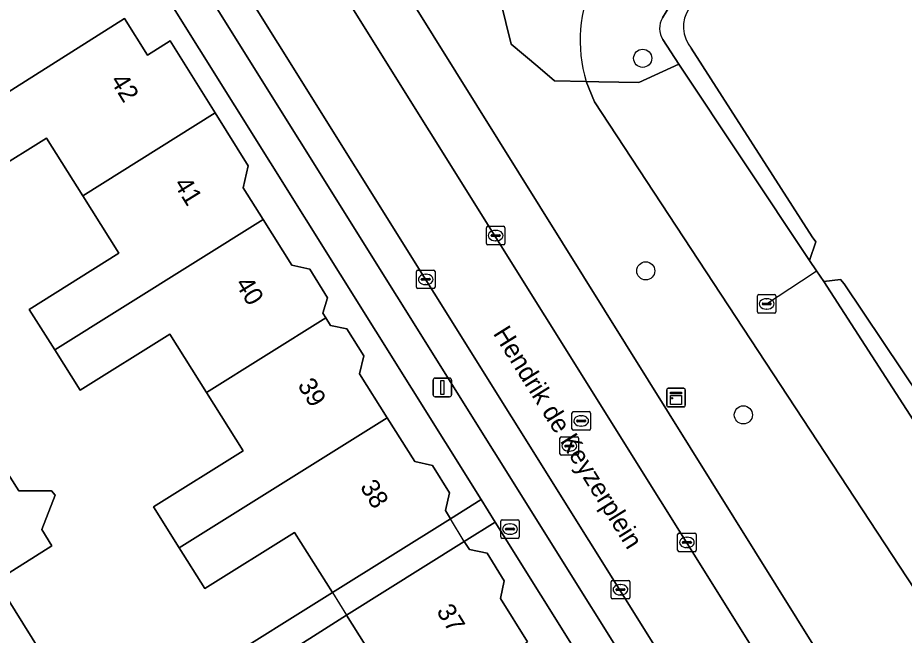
# Model space of a CAD drawing. Extents: x 159664 to 160323, y 385312 to 386115.
# Drawn here: x 159789.65 to 159837.52, y 385916.71 to 385950.06 of the extents above; entities that cross this region are included whole.
import ezdxf

# ---------------------------------------------------------------- set-up
doc = ezdxf.new("R2010")
doc.units = 0
for name, color, linetype in [('IMGEO_Boom', 7, 'Continuous'), ('IMGEO_Brandkraan', 7, 'Continuous'), ('IMGEO_Duiker', 7, 'Continuous'), ('IMGEO_Erf', 7, 'Continuous'), ('IMGEO_Groenvoorziening', 7, 'Continuous'), ('IMGEO_Kast', 7, 'Continuous'), ('IMGEO_Kolk', 7, 'Continuous'), ('IMGEO_Lichtmast', 7, 'Continuous'), ('IMGEO_Meer_plas_ven_vijver', 7, 'Continuous'), ('IMGEO_Oever', 7, 'Continuous'), ('IMGEO_Openbare_ruimte_label', 7, 'Continuous'), ('IMGEO_Pand', 7, 'Continuous'), ('IMGEO_Pand_nummerreeks', 7, 'Continuous'), ('IMGEO_Pand_overbouw', 7, 'Continuous'), ('IMGEO_Parkeervlak_open', 7, 'Continuous'), ('IMGEO_Rijbaan_lokaal_open', 7, 'Continuous'), ('IMGEO_Rioolput', 7, 'Continuous'), ('IMGEO_Voetpad_open', 7, 'Continuous')]:
    doc.layers.add(name, color=color, linetype=linetype)

msp = doc.modelspace()

# ---------------------------------------------------------------- linework, layer by layer
at = {"layer": 'IMGEO_Boom'}
for centre in [(159823.397, 385947.867), (159823.564, 385936.39), (159828.834, 385928.614)]:
    msp.add_circle(centre, 0.489, dxfattribs=at)
at = {"layer": 'IMGEO_Brandkraan'}
for p, q in [((159815.728, 385922.02), (159815.728, 385922.872)), ((159815.803, 385922.946), (159816.655, 385922.946)), ((159816.729, 385922.872), (159816.729, 385922.02)), ((159815.987, 385922.44), (159815.987, 385922.452)), ((159816.425, 385922.403), (159816.027, 385922.403)), ((159816.03, 385922.489), (159816.428, 385922.489)), ((159816.216, 385922.726), (159816.241, 385922.726)), ((159816.471, 385922.452), (159816.471, 385922.44)), ((159816.655, 385921.946), (159815.803, 385921.946)), ((159816.239, 385922.166), (159816.214, 385922.166))]:
    msp.add_line(p, q, dxfattribs=at)
for points in [[(159815.728, 385922.02), (159815.728, 385922.872)], [(159815.803, 385922.946), (159816.655, 385922.946)], [(159816.729, 385922.872), (159816.729, 385922.02)], [(159816.655, 385921.946), (159815.803, 385921.946)]]:
    msp.add_lwpolyline(points, dxfattribs=at)
for centre, radius, start, end in [((159815.805, 385922.87), 0.0765, 91.552, 178.448), ((159815.805, 385922.87), 0.0765, 91.552, 178.448), ((159816.653, 385922.87), 0.0765, 1.552, 88.448), ((159816.653, 385922.87), 0.0765, 1.552, 88.448), ((159816.027, 385922.449), 0.0403, 85.8775, 175.7526), ((159816.024, 385922.439), 0.0366, 178.938, 274.7102), ((159816.428, 385922.446), 0.043, 264.8664, 352.4533), ((159816.432, 385922.451), 0.0386, 1.7309, 96.639), ((159815.805, 385922.022), 0.0765, 181.552, 268.448), ((159815.805, 385922.022), 0.0765, 181.552, 268.448), ((159816.653, 385922.022), 0.0765, 271.552, 358.448), ((159816.653, 385922.022), 0.0765, 271.552, 358.448)]:
    msp.add_arc(centre, radius, start, end, dxfattribs=at)
for centre, major_axis, ratio, start_param, end_param in [((159816.215, 385922.446), (-0.387, 0.002), 0.722429, 4.712389, 7.853982), ((159816.24, 385922.446), (-0.39, 0.002), 0.717154, 1.570796, 4.712389)]:
    msp.add_ellipse(centre, major_axis=major_axis, ratio=ratio, start_param=start_param, end_param=end_param, dxfattribs=at)
at = {"layer": 'IMGEO_Duiker'}
msp.add_lwpolyline([(159830.09, 385934.606), (159832.603, 385936.27), (159832.783, 385936.389)], dxfattribs=at)
at = {"layer": 'IMGEO_Erf'}
for points in [[(159786.659, 385944.493), (159795.419, 385950.015), (159796.66, 385948.031), (159797.888, 385948.804), (159800.312, 385944.919), (159802.091, 385942.069), (159801.831, 385940.872), (159802.903, 385939.167), (159804.456, 385936.699), (159805.426, 385936.473), (159806.378, 385934.929), (159806.13, 385934.103), (159806.288, 385933.852), (159806.542, 385933.446), (159807.423, 385933.265), (159808.337, 385931.801), (159808.106, 385930.83), (159809.598, 385928.459), (159811.09, 385926.088), (159812.048, 385925.874), (159812.959, 385924.403), (159812.75, 385923.441), (159813.015, 385923.006), (159814.677, 385924.046), (159795.686, 385954.403)], [(159781.447, 385937.53), (159789.716, 385924.506), (159791.471, 385924.506), (159791.672, 385924.284), (159790.943, 385922.426), (159791.494, 385921.542), (159788.476, 385919.657), (159793.859, 385911.039), (159806.639, 385919.023), (159804.599, 385922.264), (159799.757, 385919.236), (159798.371, 385921.438), (159796.985, 385923.641), (159801.827, 385926.669), (159799.844, 385929.822), (159797.86, 385932.974), (159793.018, 385929.945), (159791.645, 385932.126), (159790.273, 385934.308), (159795.115, 385937.336), (159793.159, 385940.445), (159791.202, 385943.555), (159788.367, 385941.782)], [(159840.099, 385883.409), (159815.439, 385922.828), (159813.76, 385921.778), (159814.046, 385921.34), (159814.998, 385921.143), (159815.925, 385919.652), (159815.719, 385918.693), (159817.168, 385916.35)], [(159809.423, 385914.598), (159807.404, 385917.807), (159794.696, 385909.716)]]:
    msp.add_lwpolyline(points, dxfattribs=at)
at = {"layer": 'IMGEO_Groenvoorziening'}
for points in [[(159826.198, 385960.753), (159827.558, 385962.925), (159826.053, 385963.543), (159824.666, 385963.973), (159824.14, 385965.264), (159822.897, 385966.316), (159819.555, 385969.187), (159812.339, 385964.66), (159812.663, 385963.686), (159812.807, 385961.678), (159812.472, 385960.291), (159811.468, 385959.287), (159811.037, 385957.804), (159811.994, 385956.513), (159814.146, 385955.461), (159815.58, 385954.17), (159815.963, 385953.118), (159815.724, 385950.966), (159816.297, 385948.623), (159817.732, 385947.428), (159818.628, 385946.65), (159820.348, 385946.616)], [(159816.297, 385948.623), (159815.724, 385950.966), (159815.963, 385953.118), (159815.58, 385954.17), (159814.146, 385955.461), (159811.994, 385956.513), (159811.037, 385957.804), (159811.468, 385959.287), (159812.472, 385960.291), (159812.807, 385961.678), (159812.663, 385963.686), (159812.339, 385964.66), (159805.18, 385960.168), (159840.98, 385902.792), (159844.627, 385901.937), (159897.826, 385935.149), (159897.089, 385936.287), (159896.974, 385936.212), (159896.463, 385937.027)], [(159824.47, 385950.057), (159825.856, 385952.338), (159828.271, 385956.314)], [(159820.348, 385946.616), (159821.022, 385946.602), (159823.184, 385946.559), (159825.341, 385947.546), (159824.488, 385948.875)], [(159838.479, 385918.611), (159820.789, 385945.508), (159820.348, 385946.616), (159818.628, 385946.65), (159817.732, 385947.428), (159816.297, 385948.623)], [(159825.341, 385947.546), (159823.184, 385946.559), (159821.022, 385946.602), (159820.348, 385946.616), (159820.789, 385945.508), (159838.479, 385918.611), (159839.072, 385919.548), (159844.581, 385919.713), (159855.219, 385918.667), (159855.427, 385918.399), (159863.832, 385920.689), (159866.297, 385921.953), (159870.044, 385923.874), (159871.106, 385924.495), (159870.716, 385924.674), (159869.124, 385925.404), (159865.913, 385927.638), (159862.758, 385925.65), (159861.486, 385925.086), (159860.136, 385924.752), (159854.341, 385923.788), (159843.899, 385922.051)], [(159841.353, 385923.154), (159833.178, 385935.808), (159832.783, 385936.389), (159832.404, 385936.945), (159825.341, 385947.546)]]:
    msp.add_lwpolyline(points, dxfattribs=at)
for centre, radius, start, end in [((159827.47, 385948.807), 7.452, 153.2515, 197.0998), ((159827.47, 385948.807), 7.452, 153.2515, 197.0998), ((159825.421, 385949.48), 1.112, 148.7758, 212.9691)]:
    msp.add_arc(centre, radius, start, end, dxfattribs=at)
at = {"layer": 'IMGEO_Kast'}
for p, q in [((159824.695, 385929.123), (159824.695, 385929.964)), ((159824.695, 385929.964), (159824.695, 385929.123)), ((159824.77, 385930.048), (159825.611, 385930.048)), ((159825.611, 385930.048), (159824.77, 385930.048)), ((159825.695, 385929.973), (159825.695, 385929.132)), ((159825.695, 385929.132), (159825.695, 385929.973)), ((159825.62, 385929.048), (159824.779, 385929.048)), ((159824.779, 385929.048), (159825.62, 385929.048))]:
    msp.add_line(p, q, dxfattribs=at)
for points in [[(159824.89, 385929.838), (159825.49, 385929.838), (159825.49, 385929.753), (159824.89, 385929.753), (159824.89, 385929.838)], [(159824.89, 385929.663), (159825.49, 385929.663), (159825.49, 385929.174), (159824.89, 385929.174), (159824.89, 385929.663)]]:
    msp.add_lwpolyline(points, dxfattribs=at)
msp.add_circle((159824.974, 385929.512), 0.0377, dxfattribs=at)
for centre, start, end in [((159824.773, 385929.97), 92.4484, 184.2845), ((159824.773, 385929.97), 92.4484, 184.2845), ((159825.617, 385929.97), 2.4484, 94.2845), ((159825.617, 385929.97), 2.4484, 94.2845), ((159824.773, 385929.126), 182.4484, 274.2845), ((159824.773, 385929.126), 182.4484, 274.2845), ((159825.617, 385929.126), 272.4484, 4.2845), ((159825.617, 385929.126), 272.4484, 4.2845)]:
    msp.add_arc(centre, 0.0779, start, end, dxfattribs=at)
at = {"layer": 'IMGEO_Kolk'}
for p, q in [((159814.959, 385937.868), (159814.959, 385938.72)), ((159815.034, 385938.794), (159815.886, 385938.794)), ((159815.447, 385938.574), (159815.472, 385938.574)), ((159815.96, 385938.72), (159815.96, 385937.868)), ((159815.218, 385938.288), (159815.218, 385938.3)), ((159815.656, 385938.251), (159815.258, 385938.251)), ((159815.261, 385938.337), (159815.659, 385938.337)), ((159815.702, 385938.3), (159815.702, 385938.288)), ((159815.886, 385937.794), (159815.034, 385937.794)), ((159815.47, 385938.014), (159815.445, 385938.014)), ((159811.184, 385935.504), (159811.184, 385936.356)), ((159811.259, 385936.43), (159812.111, 385936.43)), ((159811.672, 385936.21), (159811.697, 385936.21)), ((159812.185, 385936.356), (159812.185, 385935.504)), ((159811.443, 385935.924), (159811.443, 385935.936)), ((159811.881, 385935.887), (159811.483, 385935.887)), ((159811.486, 385935.973), (159811.884, 385935.973)), ((159811.927, 385935.936), (159811.927, 385935.924)), ((159812.111, 385935.43), (159811.259, 385935.43)), ((159811.695, 385935.65), (159811.67, 385935.65)), ((159825.282, 385921.301), (159825.282, 385922.153)), ((159825.357, 385922.227), (159826.209, 385922.227)), ((159825.77, 385922.007), (159825.795, 385922.007)), ((159826.283, 385922.153), (159826.283, 385921.301)), ((159825.541, 385921.721), (159825.541, 385921.733)), ((159825.979, 385921.684), (159825.581, 385921.684)), ((159825.584, 385921.77), (159825.982, 385921.77)), ((159825.793, 385921.447), (159825.768, 385921.447)), ((159826.025, 385921.733), (159826.025, 385921.721)), ((159826.209, 385921.227), (159825.357, 385921.227)), ((159821.697, 385918.748), (159821.697, 385919.6)), ((159821.772, 385919.674), (159822.624, 385919.674)), ((159822.185, 385919.454), (159822.21, 385919.454)), ((159822.698, 385919.6), (159822.698, 385918.748)), ((159821.956, 385919.168), (159821.956, 385919.18)), ((159822.394, 385919.131), (159821.996, 385919.131)), ((159821.999, 385919.217), (159822.397, 385919.217)), ((159822.44, 385919.18), (159822.44, 385919.168)), ((159822.624, 385918.674), (159821.772, 385918.674)), ((159822.208, 385918.894), (159822.183, 385918.894))]:
    msp.add_line(p, q, dxfattribs=at)
for points in [[(159814.959, 385937.868), (159814.959, 385938.72)], [(159815.034, 385938.794), (159815.886, 385938.794)], [(159815.96, 385938.72), (159815.96, 385937.868)], [(159815.886, 385937.794), (159815.034, 385937.794)], [(159811.184, 385935.504), (159811.184, 385936.356)], [(159811.259, 385936.43), (159812.111, 385936.43)], [(159812.185, 385936.356), (159812.185, 385935.504)], [(159812.111, 385935.43), (159811.259, 385935.43)], [(159825.282, 385921.301), (159825.282, 385922.153)], [(159825.357, 385922.227), (159826.209, 385922.227)], [(159826.283, 385922.153), (159826.283, 385921.301)], [(159826.209, 385921.227), (159825.357, 385921.227)], [(159821.697, 385918.748), (159821.697, 385919.6)], [(159821.772, 385919.674), (159822.624, 385919.674)], [(159822.698, 385919.6), (159822.698, 385918.748)], [(159822.624, 385918.674), (159821.772, 385918.674)]]:
    msp.add_lwpolyline(points, dxfattribs=at)
for centre, radius, start, end in [((159815.036, 385938.718), 0.0765, 91.552, 178.448), ((159815.036, 385938.718), 0.0765, 91.552, 178.448), ((159815.884, 385938.718), 0.0765, 1.552, 88.448), ((159815.884, 385938.718), 0.0765, 1.552, 88.448), ((159815.258, 385938.297), 0.0403, 85.8775, 175.7526), ((159815.255, 385938.287), 0.0366, 178.938, 274.7102), ((159815.659, 385938.294), 0.043, 264.8664, 352.4533), ((159815.663, 385938.299), 0.0386, 1.7309, 96.639), ((159815.036, 385937.87), 0.0765, 181.552, 268.448), ((159815.036, 385937.87), 0.0765, 181.552, 268.448), ((159815.884, 385937.87), 0.0765, 271.552, 358.448), ((159815.884, 385937.87), 0.0765, 271.552, 358.448), ((159811.261, 385936.354), 0.0765, 91.552, 178.448), ((159811.261, 385936.354), 0.0765, 91.552, 178.448), ((159812.109, 385936.354), 0.0765, 1.552, 88.448), ((159812.109, 385936.354), 0.0765, 1.552, 88.448), ((159811.483, 385935.933), 0.0403, 85.8775, 175.7526), ((159811.48, 385935.923), 0.0366, 178.938, 274.7102), ((159811.884, 385935.93), 0.043, 264.8664, 352.4533), ((159811.888, 385935.935), 0.0386, 1.7309, 96.639), ((159811.261, 385935.506), 0.0765, 181.552, 268.448), ((159811.261, 385935.506), 0.0765, 181.552, 268.448), ((159812.109, 385935.506), 0.0765, 271.552, 358.448), ((159812.109, 385935.506), 0.0765, 271.552, 358.448), ((159825.359, 385922.151), 0.0765, 91.552, 178.448), ((159825.359, 385922.151), 0.0765, 91.552, 178.448), ((159826.207, 385922.151), 0.0765, 1.552, 88.448), ((159826.207, 385922.151), 0.0765, 1.552, 88.448), ((159825.581, 385921.73), 0.0403, 85.8775, 175.7526), ((159825.578, 385921.72), 0.0366, 178.938, 274.7102), ((159825.982, 385921.727), 0.043, 264.8664, 352.4533), ((159825.986, 385921.732), 0.0386, 1.7309, 96.639), ((159825.359, 385921.303), 0.0765, 181.552, 268.448), ((159825.359, 385921.303), 0.0765, 181.552, 268.448), ((159826.207, 385921.303), 0.0765, 271.552, 358.448), ((159826.207, 385921.303), 0.0765, 271.552, 358.448), ((159821.774, 385919.598), 0.0765, 91.552, 178.448), ((159821.774, 385919.598), 0.0765, 91.552, 178.448), ((159822.622, 385919.598), 0.0765, 1.552, 88.448), ((159822.622, 385919.598), 0.0765, 1.552, 88.448), ((159821.996, 385919.177), 0.0403, 85.8775, 175.7526), ((159821.993, 385919.167), 0.0366, 178.938, 274.7102), ((159822.397, 385919.174), 0.043, 264.8664, 352.4533), ((159822.401, 385919.179), 0.0386, 1.7309, 96.639), ((159821.774, 385918.75), 0.0765, 181.552, 268.448), ((159821.774, 385918.75), 0.0765, 181.552, 268.448), ((159822.622, 385918.75), 0.0765, 271.552, 358.448), ((159822.622, 385918.75), 0.0765, 271.552, 358.448)]:
    msp.add_arc(centre, radius, start, end, dxfattribs=at)
for centre, major_axis, ratio, start_param, end_param in [((159815.446, 385938.294), (-0.387, 0.002), 0.722429, 4.712389, 7.853982), ((159815.471, 385938.294), (-0.39, 0.002), 0.717154, 1.570796, 4.712389), ((159811.671, 385935.93), (-0.387, 0.002), 0.722429, 4.712389, 7.853982), ((159811.696, 385935.93), (-0.39, 0.002), 0.717154, 1.570796, 4.712389), ((159825.769, 385921.727), (-0.387, 0.002), 0.722429, 4.712389, 7.853982), ((159825.794, 385921.727), (-0.39, 0.002), 0.717154, 1.570796, 4.712389), ((159822.184, 385919.174), (-0.387, 0.002), 0.722429, 4.712389, 7.853982), ((159822.209, 385919.174), (-0.39, 0.002), 0.717154, 1.570796, 4.712389)]:
    msp.add_ellipse(centre, major_axis=major_axis, ratio=ratio, start_param=start_param, end_param=end_param, dxfattribs=at)
at = {"layer": 'IMGEO_Lichtmast'}
for p, q in [((159812.082, 385929.695), (159812.082, 385930.495)), ((159812.082, 385930.495), (159812.082, 385929.695)), ((159812.182, 385930.595), (159812.972, 385930.595)), ((159812.972, 385930.595), (159812.182, 385930.595)), ((159813.072, 385930.495), (159813.072, 385929.695)), ((159813.072, 385929.695), (159813.072, 385930.495)), ((159812.972, 385929.595), (159812.182, 385929.595)), ((159812.182, 385929.595), (159812.972, 385929.595))]:
    msp.add_line(p, q, dxfattribs=at)
msp.add_lwpolyline([(159812.502, 385930.47), (159812.652, 385930.47), (159812.652, 385929.72), (159812.502, 385929.72), (159812.502, 385930.47)], dxfattribs=at)
for centre, start, end in [((159812.182, 385930.495), 90, 180), ((159812.182, 385930.495), 90, 180), ((159812.972, 385930.495), 0, 90), ((159812.972, 385930.495), 360, 90), ((159812.182, 385929.695), 180, 270), ((159812.182, 385929.695), 180, 270), ((159812.972, 385929.695), 270, 0), ((159812.972, 385929.695), 270, 0)]:
    msp.add_arc(centre, 0.1, start, end, dxfattribs=at)
at = {"layer": 'IMGEO_Meer_plas_ven_vijver'}
msp.add_lwpolyline([(159826.015, 385948.406), (159832.55, 385938.234), (159832.749, 385937.963), (159832.404, 385936.945), (159832.783, 385936.389), (159833.178, 385935.808), (159834.079, 385935.928), (159834.268, 385935.688), (159842.589, 385923.279)], dxfattribs=at)
msp.add_arc((159827.404, 385949.561), 1.806, 146.1919, 219.7445, dxfattribs=at)
at = {"layer": 'IMGEO_Oever'}
for points in [[(159825.903, 385950.566), (159826.708, 385951.882), (159825.856, 385952.338), (159824.47, 385950.057)], [(159824.488, 385948.875), (159825.341, 385947.546), (159832.404, 385936.945), (159832.749, 385937.963), (159832.55, 385938.234), (159826.015, 385948.406)], [(159842.589, 385923.279), (159834.268, 385935.688), (159834.079, 385935.928), (159833.178, 385935.808), (159841.353, 385923.154)]]:
    msp.add_lwpolyline(points, dxfattribs=at)
for centre, radius, start, end in [((159827.404, 385949.561), 1.806, 146.1919, 219.7445), ((159825.421, 385949.48), 1.112, 148.7758, 212.9691)]:
    msp.add_arc(centre, radius, start, end, dxfattribs=at)
at = {"layer": 'IMGEO_Pand'}
for points in [[(159800.312, 385944.919), (159797.888, 385948.804), (159796.66, 385948.031), (159795.419, 385950.015), (159786.659, 385944.493), (159788.367, 385941.782), (159791.202, 385943.555), (159793.159, 385940.445)], [(159802.903, 385939.167), (159801.831, 385940.872), (159802.091, 385942.069), (159800.312, 385944.919), (159793.159, 385940.445), (159795.115, 385937.336), (159790.273, 385934.308), (159791.645, 385932.126)], [(159791.645, 385932.126), (159793.018, 385929.945), (159797.86, 385932.974), (159799.844, 385929.822), (159806.288, 385933.852), (159806.13, 385934.103), (159806.378, 385934.929), (159805.426, 385936.473), (159804.456, 385936.699), (159802.903, 385939.167)], [(159799.844, 385929.822), (159801.827, 385926.669), (159796.985, 385923.641), (159798.371, 385921.438), (159809.598, 385928.459), (159808.106, 385930.83), (159808.337, 385931.801), (159807.423, 385933.265), (159806.542, 385933.446), (159806.288, 385933.852)], [(159813.015, 385923.006), (159812.75, 385923.441), (159812.959, 385924.403), (159812.048, 385925.874), (159811.09, 385926.088), (159809.598, 385928.459), (159798.371, 385921.438), (159799.757, 385919.236), (159804.599, 385922.264), (159806.639, 385919.023)], [(159807.404, 385917.807), (159809.423, 385914.598), (159804.58, 385911.57), (159805.973, 385909.356), (159817.168, 385916.35), (159815.719, 385918.693), (159815.925, 385919.652), (159814.998, 385921.143), (159814.046, 385921.34), (159813.76, 385921.778)]]:
    msp.add_lwpolyline(points, close=True, dxfattribs=at)
at = {"layer": 'IMGEO_Pand_overbouw'}
msp.add_lwpolyline([(159813.015, 385923.006), (159806.639, 385919.023), (159807.404, 385917.807), (159813.76, 385921.778)], close=True, dxfattribs=at)
at = {"layer": 'IMGEO_Parkeervlak_open'}
for points in [[(159833.101, 385901.651), (159799.513, 385955.383)], [(159799.613, 385951.857), (159841.754, 385884.442), (159843.279, 385885.394), (159833.101, 385901.651)]]:
    msp.add_lwpolyline(points, dxfattribs=at)
at = {"layer": 'IMGEO_Rijbaan_lokaal_open'}
msp.add_lwpolyline([(159805.626, 385953.958), (159802.692, 385958.777), (159798.855, 385956.375), (159799.513, 385955.383), (159833.101, 385901.651), (159836.858, 385903.992)], close=True, dxfattribs=at)
at = {"layer": 'IMGEO_Rioolput'}
for p, q in [((159829.589, 385934.18), (159829.589, 385935.032)), ((159829.664, 385935.106), (159830.516, 385935.106)), ((159830.077, 385934.886), (159830.102, 385934.886)), ((159830.59, 385935.032), (159830.59, 385934.18)), ((159829.848, 385934.6), (159829.848, 385934.612)), ((159830.286, 385934.563), (159829.888, 385934.563)), ((159829.891, 385934.649), (159830.289, 385934.649)), ((159830.1, 385934.326), (159830.075, 385934.326)), ((159830.332, 385934.612), (159830.332, 385934.6)), ((159830.516, 385934.106), (159829.664, 385934.106)), ((159819.575, 385927.861), (159819.575, 385928.713)), ((159819.65, 385928.787), (159820.502, 385928.787)), ((159820.063, 385928.567), (159820.088, 385928.567)), ((159820.576, 385928.713), (159820.576, 385927.861)), ((159819.834, 385928.281), (159819.834, 385928.293)), ((159820.272, 385928.244), (159819.874, 385928.244)), ((159819.877, 385928.33), (159820.275, 385928.33)), ((159820.318, 385928.293), (159820.318, 385928.281)), ((159820.502, 385927.787), (159819.65, 385927.787)), ((159820.086, 385928.007), (159820.061, 385928.007)), ((159818.931, 385926.508), (159818.931, 385927.36)), ((159819.006, 385927.434), (159819.858, 385927.434)), ((159819.419, 385927.214), (159819.444, 385927.214)), ((159819.932, 385927.36), (159819.932, 385926.508)), ((159819.19, 385926.928), (159819.19, 385926.94)), ((159819.628, 385926.891), (159819.23, 385926.891)), ((159819.233, 385926.977), (159819.631, 385926.977)), ((159819.442, 385926.654), (159819.417, 385926.654)), ((159819.674, 385926.94), (159819.674, 385926.928)), ((159819.858, 385926.434), (159819.006, 385926.434))]:
    msp.add_line(p, q, dxfattribs=at)
for points in [[(159829.589, 385934.18), (159829.589, 385935.032)], [(159829.664, 385935.106), (159830.516, 385935.106)], [(159830.59, 385935.032), (159830.59, 385934.18)], [(159830.516, 385934.106), (159829.664, 385934.106)], [(159819.575, 385927.861), (159819.575, 385928.713)], [(159819.65, 385928.787), (159820.502, 385928.787)], [(159820.576, 385928.713), (159820.576, 385927.861)], [(159820.502, 385927.787), (159819.65, 385927.787)], [(159818.931, 385926.508), (159818.931, 385927.36)], [(159819.006, 385927.434), (159819.858, 385927.434)], [(159819.932, 385927.36), (159819.932, 385926.508)], [(159819.858, 385926.434), (159819.006, 385926.434)]]:
    msp.add_lwpolyline(points, dxfattribs=at)
for centre, radius, start, end in [((159829.666, 385935.03), 0.0765, 91.552, 178.448), ((159829.666, 385935.03), 0.0765, 91.552, 178.448), ((159830.514, 385935.03), 0.0765, 1.552, 88.448), ((159830.514, 385935.03), 0.0765, 1.552, 88.448), ((159829.888, 385934.609), 0.0403, 85.8775, 175.7526), ((159829.885, 385934.599), 0.0366, 178.938, 274.7102), ((159830.289, 385934.606), 0.043, 264.8664, 352.4533), ((159830.293, 385934.611), 0.0386, 1.7309, 96.639), ((159829.666, 385934.182), 0.0765, 181.552, 268.448), ((159829.666, 385934.182), 0.0765, 181.552, 268.448), ((159830.514, 385934.182), 0.0765, 271.552, 358.448), ((159830.514, 385934.182), 0.0765, 271.552, 358.448), ((159819.652, 385928.711), 0.0765, 91.552, 178.448), ((159819.652, 385928.711), 0.0765, 91.552, 178.448), ((159820.5, 385928.711), 0.0765, 1.552, 88.448), ((159820.5, 385928.711), 0.0765, 1.552, 88.448), ((159819.874, 385928.29), 0.0403, 85.8775, 175.7526), ((159819.871, 385928.28), 0.0366, 178.938, 274.7102), ((159820.275, 385928.287), 0.043, 264.8664, 352.4533), ((159820.279, 385928.292), 0.0386, 1.7309, 96.639), ((159819.652, 385927.863), 0.0765, 181.552, 268.448), ((159819.652, 385927.863), 0.0765, 181.552, 268.448), ((159820.5, 385927.863), 0.0765, 271.552, 358.448), ((159820.5, 385927.863), 0.0765, 271.552, 358.448), ((159819.008, 385927.358), 0.0765, 91.552, 178.448), ((159819.008, 385927.358), 0.0765, 91.552, 178.448), ((159819.856, 385927.358), 0.0765, 1.552, 88.448), ((159819.856, 385927.358), 0.0765, 1.552, 88.448), ((159819.23, 385926.937), 0.0403, 85.8775, 175.7526), ((159819.227, 385926.927), 0.0366, 178.938, 274.7102), ((159819.631, 385926.934), 0.043, 264.8664, 352.4533), ((159819.635, 385926.939), 0.0386, 1.7309, 96.639), ((159819.008, 385926.51), 0.0765, 181.552, 268.448), ((159819.008, 385926.51), 0.0765, 181.552, 268.448), ((159819.856, 385926.51), 0.0765, 271.552, 358.448), ((159819.856, 385926.51), 0.0765, 271.552, 358.448)]:
    msp.add_arc(centre, radius, start, end, dxfattribs=at)
for centre, major_axis, ratio, start_param, end_param in [((159830.076, 385934.606), (-0.387, 0.002), 0.722429, 4.712389, 7.853982), ((159830.101, 385934.606), (-0.39, 0.002), 0.717154, 1.570796, 4.712389), ((159820.062, 385928.287), (-0.387, 0.002), 0.722429, 4.712389, 7.853982), ((159820.087, 385928.287), (-0.39, 0.002), 0.717154, 1.570796, 4.712389), ((159819.418, 385926.934), (-0.387, 0.002), 0.722429, 4.712389, 7.853982), ((159819.443, 385926.934), (-0.39, 0.002), 0.717154, 1.570796, 4.712389)]:
    msp.add_ellipse(centre, major_axis=major_axis, ratio=ratio, start_param=start_param, end_param=end_param, dxfattribs=at)
at = {"layer": 'IMGEO_Voetpad_open'}
for points in [[(159805.18, 385960.168), (159802.692, 385958.777), (159805.626, 385953.958), (159836.858, 385903.992), (159837.407, 385903.15)], [(159842.724, 385899.996), (159840.98, 385902.792), (159805.18, 385960.168)], [(159799.513, 385955.383), (159798.855, 385956.375), (159795.686, 385954.403), (159814.677, 385924.046), (159815.439, 385922.828), (159840.099, 385883.409), (159841.754, 385884.442), (159799.613, 385951.857)], [(159794.696, 385909.716), (159807.404, 385917.807), (159813.76, 385921.778), (159815.439, 385922.828), (159814.677, 385924.046), (159813.015, 385923.006), (159806.639, 385919.023), (159793.859, 385911.039), (159788.476, 385919.657), (159791.494, 385921.542), (159790.943, 385922.426), (159791.672, 385924.284), (159791.471, 385924.506), (159789.716, 385924.506), (159781.447, 385937.53)]]:
    msp.add_lwpolyline(points, dxfattribs=at)

# ---------------------------------------------------------------- texts
at = {"layer": 'IMGEO_Openbare_ruimte_label'}
msp.add_text('Hendrik de Keyzerplein', height=1, rotation=301.9265, dxfattribs=at).set_placement((159815.293, 385933.012))
at = {"layer": 'IMGEO_Pand_nummerreeks'}
for s, rotation, p in [('42', 301.5891, (159794.617, 385946.664)), ('41', 301.5891, (159798.049, 385941.083)), ('40', 301.5891, (159801.363, 385935.695)), ('39', 301.5891, (159804.733, 385930.215)), ('38', 301.5891, (159808.105, 385924.731)), ('37', 301.717, (159812.231, 385918.016))]:
    msp.add_text(s, height=1, rotation=rotation, dxfattribs=at).set_placement(p)

doc.saveas('drawing.dxf')
